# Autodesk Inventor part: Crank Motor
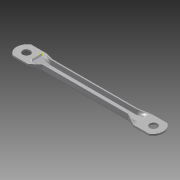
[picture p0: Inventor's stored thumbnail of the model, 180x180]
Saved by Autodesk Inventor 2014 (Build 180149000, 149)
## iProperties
Created: 2006-03
Part Number: Crank Motor
Document SubType Name: Modeling
Designer: Autodesk, Inc.
Material: Stainless Steel, 440C
Mass: 59.5791 g
Surface Area: 96.204 cm^2
Volume: 7.68763 cm^3
Density: 7.75 g/cm^3
Appearance: Steel
Author: Autodesk, Inc.
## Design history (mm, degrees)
sketch "Sketch1"
  geometry: L1 (0, 0)-(0, 1.6); L2 (0, 1.6)-(4.6, 1.6); L3 (4.6, 1.6)-(4.6, 8); L4 (4.6, 8)-(6.2, 8); L5 (6.2, 8)-(6.2, 1.5); L6 (4.7, 0)-(0, 0); L7 (0, 9.662)-(0, -1.973) reference; L8 (-4.6, 1.6)-(-4.6, 8); L9 (-4.6, 8)-(-6.2, 8); L10 (-6.2, 8)-(-6.2, 1.5); L11 (0, 1.6)-(-4.6, 1.6); L12 (-4.7, 0)-(0, 0); A1 r 1.5 centre (4.7, 1.5) between (4.7, 0) and (6.2, 1.5); A2 r 1.5 centre (-4.7, 1.5) between (-6.2, 1.5) and (-4.7, 0)
  constraints: 22 end point, 6 symmetric about line, 4 parallel, 4 point on circle, 2 centre point, 2 perpendicular, 2 tangent, 1 vertical, 1 other
  dimensions: "d1" = 4.6 distance between parallel lines of L3 L1; "d2" = 8 distance between parallel lines of L6 L4; "d3" = 1.6 distance between parallel lines of L5 L3; "d4" = 1.5 radius of A1
extrude "Extrusion1" new body sketch "Sketch1" distance "d5" = 55.6; taper "d6" = 0 deg
workplane "Work Plane1"
sketch "Sketch2"
  geometry: L1 (-1.6, 0)-(9.6, 0) reference; L2 (3, 12)-(5, 12); L3 (5, 12)-(5, -12); L4 (5, -12)-(3, -12); L5 (3, -12)-(3, 12); L6 (3, 12)-(5, -12); L7 (1.5, 6.2)-(8, 6.2) reference; L8 (8, -6.2)-(1.5, -6.2) reference; L9 (0, -4.7)-(0, 4.7) reference; 2 further points
  constraints: 10 end point, 2 midpoint, 2 parallel, 1 horizontal, 1 perpendicular
  dimensions: "d8" = 4 distance from line of point (4, 0) L9; "d9" = 2 distance of L2.start L2.end; "d10" = 24 distance of L2.end L3.end
loft "Loft1" sketch "Sketch2" dims "d11" = 0, "d12" = 90 deg, "d13" = 0, "d14" = 90 deg
  node "Edges1"
sketch "Sketch3"
  geometry: L1 (2, 12.374)-(2, 18.469) reference; L2 (2, 19.993)-(0, 19.993) reference; L3 (2, 18.469)-(2, 19.993) reference; L4 (2, 3.612)-(2, 12.374) reference; L5 (2, -2.483)-(2, 3.612) reference; L6 (2, -4.007)-(2, -2.483) reference; L7 (0, -4.007)-(2, -4.007) reference; L8 (0, 0)-(0, -4.007) reference; L9 (0, 15.986)-(0, 0) reference; L10 (0, 19.993)-(0, 15.986) reference; 1 further point
extrude "Extrusion2" join sketch "Sketch3" distance "d15" = 20; taper "d16" = 0 deg
sketch "Sketch4"
  geometry: L1 (-25.867, 12)-(107.678, 12) reference; L2 (0, 24)-(0, 0); A1 r 14 centre (7.211, 12) between (0, 24) and (0, 0); 1 further point
  constraints: 3 point on circle, 2 end point, 1 centre point, 1 perpendicular, 1 point on line
  dimensions: "d17" = 14 radius of A1
extrude "Extrusion3" join sketch "Sketch4" stored distance "d18" = 20; taper "d19" = 0 deg
sketch "Sketch5"
  geometry: L1 (-45.867, 4.381)-(87.678, 4.381) reference; L2 (0, 12.374)-(0, -3.612) reference; C1 r 5 at (-14, 4.381); 1 further point
  constraints: 1 centre point, 1 point on line
  dimensions: "d20" = 10 diameter of C1; "d21" = 14 distance from line of C1.centre L2
extrude "Extrusion4" cut sketch "Sketch5" stored distance "d22" = 20; taper "d23" = 0 deg
mirror "Mirror1"
body "Solid1"
other parameters: "d7" = 13
